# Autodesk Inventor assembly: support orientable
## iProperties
Shininess: 41.0
Length Units: 11269
Angle Units: 11279
Time Units: 11290
Mass Units: 11283
Length Display Precision: 3
Angle Display Precision: 2
Created: 2002-05
Part Number: support orientable
Document SubType Name: Assemblage
Designer: REVEST Pierre
Density: 0.0
Volumn: 0.0
Area: 0.0
PropertySet Name: Model Information
Control State: 0
Master: False
Checked Out: False
Author: REVEST Pierre
